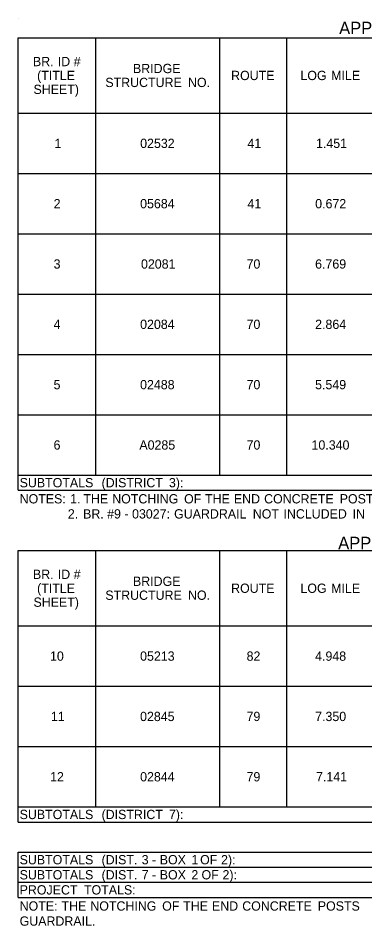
# Model space of a CAD drawing. Extents: x 544478 to 1930787, y -1948294 to 596640.
# Drawn here: x 559564 to 559788, y -1946745 to -1946159 of the extents above; entities that cross this region are included whole.
import ezdxf

# ---------------------------------------------------------------- set-up
doc = ezdxf.new("R2010")
doc.units = 0
doc.layers.add('Default', color=7, linetype='Continuous')

msp = doc.modelspace()

# ---------------------------------------------------------------- linework, layer by layer
at = {"layer": 'Default'}
for p, q in [((559563.64, -1946158.53), (559563.64, -1946158.53)), ((559563.64, -1946171.21), (560213.97, -1946171.21)), ((559563.64, -1946463.71), (559563.64, -1946171.21)), ((559613.85, -1946453.96), (559613.85, -1946171.21)), ((559694.29, -1946453.96), (559694.29, -1946171.21)), ((559737.68, -1946453.96), (559737.68, -1946171.21)), ((559563.64, -1946219.96), (560213.97, -1946219.96)), ((559563.64, -1946258.96), (560213.97, -1946258.96)), ((559563.64, -1946297.96), (560213.97, -1946297.96)), ((559563.64, -1946336.96), (560213.97, -1946336.96)), ((559563.64, -1946375.96), (560213.97, -1946375.96)), ((559563.64, -1946414.96), (560213.97, -1946414.96)), ((559563.64, -1946453.96), (560213.97, -1946453.96)), ((559563.64, -1946463.71), (560213.97, -1946463.71)), ((559563.64, -1946502.71), (560213.97, -1946502.71)), ((559563.64, -1946678.21), (559563.64, -1946502.71)), ((559613.85, -1946668.46), (559613.85, -1946502.71)), ((559694.29, -1946668.46), (559694.29, -1946502.71)), ((559737.68, -1946668.46), (559737.68, -1946502.71)), ((559563.64, -1946551.46), (560213.97, -1946551.46)), ((559563.64, -1946590.46), (560213.97, -1946590.46)), ((559563.64, -1946629.46), (560213.97, -1946629.46)), ((559563.64, -1946668.46), (560213.97, -1946668.46)), ((559563.64, -1946678.21), (560213.97, -1946678.21)), ((559563.64, -1946697.71), (560213.97, -1946697.71)), ((559563.64, -1946697.71), (560213.97, -1946697.71)), ((559563.64, -1946726.96), (559563.64, -1946697.71)), ((559563.64, -1946707.46), (560213.97, -1946707.46)), ((559563.64, -1946717.21), (560213.97, -1946717.21)), ((559563.64, -1946726.96), (560213.97, -1946726.96))]:
    msp.add_line(p, q, dxfattribs=at)

# ---------------------------------------------------------------- texts
for s, height, p in [('APPROACH', 8, (559771.47, -1946168.87)), ('BR.', 6, (559573.23, -1946189.58)), (' ID', 6, (559587.09, -1946189.58)), (' #', 6, (559597.38, -1946189.58)), ('BRIDGE', 6, (559637.98, -1946194.08)), ('(TITLE', 6, (559575.92, -1946198.58)), ('ROUTE', 6, (559701.52, -1946198.58)), ('LOG', 6, (559746.4, -1946198.58)), (' MILE', 6, (559764.06, -1946198.58)), ('SHEET)', 6, (559573.59, -1946207.58)), ('STRUCTURE', 6, (559620.1, -1946203.08)), (' NO.', 6, (559671.39, -1946203.08)), ('1', 6, (559587.19, -1946242.46)), ('02532', 6, (559642.65, -1946242.46)), ('41', 6, (559712.1, -1946242.46)), ('1.451', 6, (559756.49, -1946242.46)), ('2', 6, (559586.64, -1946281.46)), ('05684', 6, (559642.63, -1946281.46)), ('41', 6, (559712.1, -1946281.46)), ('0.672', 6, (559755.94, -1946281.46)), ('3', 6, (559586.61, -1946320.46)), ('02081', 6, (559643.19, -1946320.46)), ('70', 6, (559711.53, -1946320.46)), ('6.769', 6, (559755.9, -1946320.46)), ('4', 6, (559586.62, -1946359.46)), ('02084', 6, (559642.63, -1946359.46)), ('70', 6, (559711.53, -1946359.46)), ('2.864', 6, (559755.92, -1946359.46)), ('5', 6, (559586.59, -1946398.46)), ('02488', 6, (559642.61, -1946398.46)), ('70', 6, (559711.53, -1946398.46)), ('5.549', 6, (559755.9, -1946398.46)), ('6', 6, (559586.61, -1946437.46)), ('A0285', 6, (559642.12, -1946437.46)), ('70', 6, (559711.53, -1946437.46)), ('10.340', 6, (559753.59, -1946437.46)), ('SUBTOTALS', 6, (559564.62, -1946461.83)), (' (DISTRICT', 6, (559615.44, -1946461.83)), (' 3):', 6, (559659.04, -1946461.83)), ('NOTES:', 6, (559564.62, -1946472.26)), (' 1.', 6, (559595.1, -1946472.26)), (' THE', 6, (559603.68, -1946472.26)), (' NOTCHING', 6, (559622.33, -1946472.26)), (' OF', 6, (559668.84, -1946472.26)), (' THE', 6, (559682.43, -1946472.26)), (' END', 6, (559701.08, -1946472.26)), (' CONCRETE', 6, (559720.66, -1946472.26)), (' POSTS', 6, (559769.59, -1946472.26)), ('              2.', 6, (559564.62, -1946482.01)), (' BR.', 6, (559603.46, -1946482.01)), (' #9', 6, (559619.03, -1946482.01)), (' 03027:', 6, (559635.17, -1946482.01)), (' GUARDRAIL', 6, (559662.39, -1946482.01)), (' NOT', 6, (559713.34, -1946482.01)), (' INCLUDED', 6, (559733.19, -1946482.01)), (' IN', 6, (559777.93, -1946482.01)), (' -', 6, (559630.31, -1946482.01)), ('APPROACH', 8, (559770.85, -1946501.83)), ('BR.', 6, (559573.23, -1946521.08)), (' ID', 6, (559587.09, -1946521.08)), (' #', 6, (559597.38, -1946521.08)), ('BRIDGE', 6, (559637.98, -1946525.58)), ('(TITLE', 6, (559575.92, -1946530.08)), ('ROUTE', 6, (559701.52, -1946530.08)), ('LOG', 6, (559746.4, -1946530.08)), (' MILE', 6, (559764.06, -1946530.08)), ('STRUCTURE', 6, (559620.1, -1946534.58)), (' NO.', 6, (559671.39, -1946534.58)), ('SHEET)', 6, (559573.59, -1946539.08)), ('10', 6, (559584.29, -1946573.96)), ('05213', 6, (559642.61, -1946573.96)), ('82', 6, (559711.55, -1946573.96)), ('4.948', 6, (559755.9, -1946573.96)), ('11', 6, (559584.86, -1946612.96)), ('02845', 6, (559642.59, -1946612.96)), ('79', 6, (559711.51, -1946612.96)), ('7.350', 6, (559755.92, -1946612.96)), ('12', 6, (559584.31, -1946651.96)), ('02844', 6, (559642.63, -1946651.96)), ('79', 6, (559711.51, -1946651.96)), ('7.141', 6, (559756.49, -1946651.96)), ('SUBTOTALS', 6, (559564.62, -1946676.33)), (' (DISTRICT', 6, (559615.44, -1946676.33)), (' 7):', 6, (559659.04, -1946676.33)), ('SUBTOTALS', 6, (559564.62, -1946705.58)), (' (DIST.', 6, (559615.44, -1946705.58)), (' 3', 6, (559641.41, -1946705.58)), (' BOX', 6, (559653.09, -1946705.58)), (' 1', 6, (559673.58, -1946705.58)), (' OF', 6, (559679.21, -1946705.58)), (' 2):', 6, (559692.79, -1946705.58)), (' -', 6, (559648.04, -1946705.58)), ('SUBTOTALS', 6, (559564.62, -1946715.33)), (' (DIST.', 6, (559615.44, -1946715.33)), (' 7', 6, (559641.41, -1946715.33)), (' -', 6, (559648.03, -1946715.33)), (' BOX', 6, (559653.09, -1946715.33)), (' 2', 6, (559673.57, -1946715.33)), (' OF', 6, (559680.14, -1946715.33)), (' 2):', 6, (559693.72, -1946715.33)), ('PROJECT', 6, (559564.62, -1946725.08)), (' TOTALS:', 6, (559604.04, -1946725.08)), ('NOTE:', 6, (559564.62, -1946735.51)), (' THE', 6, (559589.5, -1946735.51)), (' NOTCHING', 6, (559608.15, -1946735.51)), (' OF', 6, (559654.67, -1946735.51)), (' THE', 6, (559668.25, -1946735.51)), (' END', 6, (559686.9, -1946735.51)), (' CONCRETE', 6, (559706.49, -1946735.51)), (' POSTS', 6, (559755.41, -1946735.51)), ('GUARDRAIL.', 6, (559564.62, -1946745.26))]:
    msp.add_text(s, height=height, dxfattribs=at).set_placement(p)

doc.saveas('drawing.dxf')
